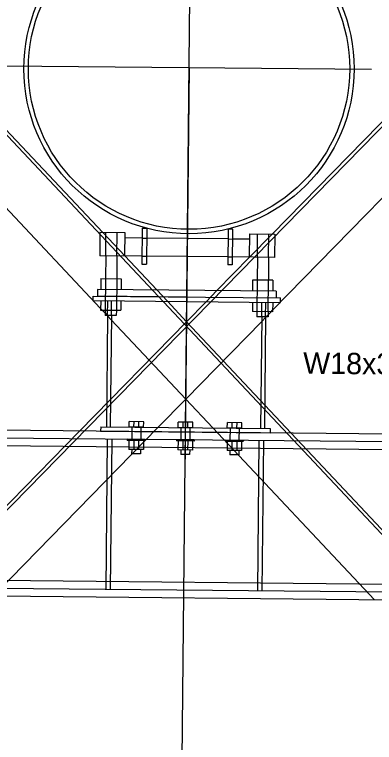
# Model space of a CAD drawing. Extents: x 632312 to 632885, y 378199 to 378534.
# Drawn here: x 632344.73 to 632348.09, y 378386.07 to 378392.88 of the extents above; entities that cross this region are included whole.
import ezdxf

# ---------------------------------------------------------------- set-up
doc = ezdxf.new("R2010")
doc.units = 0
for name, color, linetype in [('B_Boring', 7, 'Continuous'), ('R_Proposed Const Limits Cut', 7, 'Continuous'), ('R_Road Edge of Shoulder', 7, 'Continuous'), ('SHT_Dimensions', 7, 'Continuous')]:
    doc.layers.add(name, color=color, linetype=linetype)

msp = doc.modelspace()

# ---------------------------------------------------------------- linework, layer by layer
at = {"layer": 'B_Boring'}
for p, q in [((632345.9195, 378390.881), (632345.9162, 378390.5452)), ((632345.9195, 378390.881), (632345.9606, 378390.8806)), ((632345.9606, 378390.8806), (632345.9573, 378390.5448)), ((632346.7211, 378390.873), (632346.7178, 378390.5372)), ((632346.7622, 378390.8726), (632346.7211, 378390.873)), ((632346.7622, 378390.8726), (632346.7588, 378390.5368)), ((632345.5242, 378390.8408), (632345.522, 378390.624)), ((632345.7583, 378390.8385), (632345.5242, 378390.8408)), ((632345.7561, 378390.6217), (632345.7583, 378390.8385)), ((632345.9186, 378390.7881), (632345.7578, 378390.7897)), ((632346.7202, 378390.7801), (632345.9597, 378390.7877)), ((632346.922, 378390.7781), (632346.7612, 378390.7797)), ((632346.9204, 378390.6101), (632346.9225, 378390.8269)), ((632346.9225, 378390.8269), (632347.1566, 378390.8246)), ((632347.1566, 378390.8246), (632347.1545, 378390.6078)), ((632345.9169, 378390.6201), (632345.522, 378390.624)), ((632345.5776, 378390.6235), (632345.5754, 378390.41)), ((632345.6824, 378390.6224), (632345.6802, 378390.4089)), ((632346.7185, 378390.6121), (632345.958, 378390.6197)), ((632347.1545, 378390.6078), (632346.7596, 378390.6117)), ((632346.9942, 378390.6094), (632346.992, 378390.3959)), ((632347.0989, 378390.6083), (632347.0968, 378390.3949)), ((632345.9162, 378390.5452), (632345.9573, 378390.5448)), ((632346.7588, 378390.5368), (632346.7178, 378390.5372)), ((632345.5332, 378390.4104), (632345.5322, 378390.3083)), ((632345.5332, 378390.4104), (632345.7224, 378390.4085)), ((632345.7224, 378390.4085), (632345.7214, 378390.3064)), ((632346.9498, 378390.3963), (632346.9488, 378390.2942)), ((632347.139, 378390.3944), (632346.9498, 378390.3963)), ((632347.139, 378390.3944), (632347.138, 378390.2923)), ((632345.5018, 378390.3086), (632345.5012, 378390.2454)), ((632347.1684, 378390.292), (632345.5018, 378390.3086)), ((632345.4591, 378390.2041), (632345.4595, 378390.2458)), ((632345.4595, 378390.2458), (632347.2094, 378390.2284)), ((632347.1684, 378390.292), (632347.1678, 378390.2288)), ((632345.4591, 378390.2041), (632347.209, 378390.1867)), ((632345.5312, 378390.2034), (632345.5303, 378390.1154)), ((632345.7204, 378390.2015), (632345.7195, 378390.1135)), ((632346.9478, 378390.1893), (632346.9469, 378390.1013)), ((632347.137, 378390.1874), (632347.1361, 378390.0994)), ((632347.209, 378390.1867), (632347.2094, 378390.2284)), ((632345.5303, 378390.1154), (632345.7195, 378390.1135)), ((632345.5725, 378390.115), (632345.572, 378390.0659)), ((632345.6773, 378390.1139), (632345.6768, 378390.0649)), ((632347.1361, 378390.0994), (632346.9469, 378390.1013)), ((632346.9891, 378390.1009), (632346.9886, 378390.0519)), ((632347.0939, 378390.0998), (632347.0934, 378390.0508)), ((632345.6768, 378390.0649), (632345.572, 378390.0659)), ((632345.5952, 378390.0657), (632345.5849, 378389.0232)), ((632345.6307, 378390.0654), (632345.6203, 378389.0228)), ((632347.0934, 378390.0508), (632346.9886, 378390.0519)), ((632347.0348, 378390.0514), (632347.0244, 378389.0089)), ((632347.0702, 378390.051), (632347.0598, 378389.0085)), ((632345.7963, 378389.0211), (632345.7969, 378389.0732)), ((632345.9322, 378389.0718), (632345.7969, 378389.0732)), ((632345.8415, 378389.0206), (632345.842, 378389.0727)), ((632351.8217, 378388.9195), (632340.8222, 378389.0289)), ((632345.5307, 378389.0237), (632345.5303, 378388.982)), ((632345.5307, 378389.0237), (632347.114, 378389.008)), ((632345.9317, 378389.0197), (632345.7963, 378389.0211)), ((632345.8224, 378389.0208), (632345.8212, 378388.9067)), ((632345.8866, 378389.0202), (632345.8871, 378389.0723)), ((632345.9057, 378389.02), (632345.9046, 378388.9058)), ((632345.9317, 378389.0197), (632345.9322, 378389.0718)), ((632346.2546, 378389.0165), (632346.2552, 378389.0686)), ((632346.39, 378389.0152), (632346.2546, 378389.0165)), ((632346.3906, 378389.0673), (632346.2552, 378389.0686)), ((632346.2807, 378389.0163), (632346.2795, 378388.9021)), ((632346.2998, 378389.0161), (632346.3003, 378389.0682)), ((632346.3449, 378389.0156), (632346.3454, 378389.0677)), ((632346.364, 378389.0155), (632346.3629, 378388.9013)), ((632346.39, 378389.0152), (632346.3906, 378389.0673)), ((632346.713, 378389.012), (632346.7135, 378389.0641)), ((632346.8484, 378389.0106), (632346.713, 378389.012)), ((632346.8489, 378389.0627), (632346.7135, 378389.0641)), ((632346.739, 378389.0117), (632346.7379, 378388.8976)), ((632346.7581, 378389.0115), (632346.7586, 378389.0636)), ((632346.8032, 378389.0111), (632346.8037, 378389.0632)), ((632346.8223, 378389.0109), (632346.8212, 378388.8967)), ((632346.8484, 378389.0106), (632346.8489, 378389.0627)), ((632347.114, 378389.008), (632347.1135, 378388.9663)), ((632351.8209, 378388.847), (632340.8215, 378388.9564)), ((632345.5303, 378388.9821), (632347.1135, 378388.9663)), ((632345.5921, 378388.909), (632345.5781, 378387.504)), ((632345.6337, 378388.9085), (632345.6198, 378387.5036)), ((632345.7796, 378388.9071), (632345.7795, 378388.8967)), ((632345.9461, 378388.895), (632345.7795, 378388.8967)), ((632345.9462, 378388.9054), (632345.7796, 378388.9071)), ((632345.7951, 378388.8965), (632345.7943, 378388.8132)), ((632345.8402, 378388.8961), (632345.8394, 378388.8127)), ((632345.8854, 378388.8956), (632345.8845, 378388.8123)), ((632345.9305, 378388.8952), (632345.9297, 378388.8118)), ((632345.9462, 378388.9054), (632345.9461, 378388.895)), ((632346.2379, 378388.9025), (632346.2378, 378388.8921)), ((632346.4044, 378388.8905), (632346.2378, 378388.8921)), ((632346.4045, 378388.9009), (632346.2379, 378388.9025)), ((632346.2534, 378388.892), (632346.2526, 378388.8086)), ((632346.2985, 378388.8915), (632346.2977, 378388.8082)), ((632346.3437, 378388.8911), (632346.3428, 378388.8077)), ((632346.3888, 378388.8906), (632346.388, 378388.8073)), ((632346.4045, 378388.9009), (632346.4044, 378388.8905)), ((632346.6962, 378388.898), (632346.6961, 378388.8876)), ((632346.8627, 378388.8859), (632346.6961, 378388.8876)), ((632346.8628, 378388.8963), (632346.6962, 378388.898)), ((632346.7117, 378388.8874), (632346.7109, 378388.8041)), ((632346.7568, 378388.887), (632346.756, 378388.8036)), ((632346.802, 378388.8865), (632346.8012, 378388.8032)), ((632346.8471, 378388.8861), (632346.8463, 378388.8027)), ((632346.8628, 378388.8963), (632346.8627, 378388.8859)), ((632347.0087, 378388.8949), (632346.9947, 378387.4899)), ((632347.0503, 378388.8945), (632347.0364, 378387.4895)), ((632345.9297, 378388.8118), (632345.7943, 378388.8132)), ((632345.8203, 378388.8129), (632345.8199, 378388.7713)), ((632345.9036, 378388.8121), (632345.9032, 378388.7704)), ((632346.388, 378388.8073), (632346.2526, 378388.8086)), ((632346.2786, 378388.8084), (632346.2782, 378388.7667)), ((632346.3619, 378388.8075), (632346.3615, 378388.7659)), ((632346.8463, 378388.8027), (632346.7109, 378388.8041)), ((632346.7369, 378388.8038), (632346.7365, 378388.7622)), ((632346.8203, 378388.803), (632346.8198, 378388.7613)), ((632345.9032, 378388.7704), (632345.8199, 378388.7713)), ((632346.3615, 378388.7659), (632346.2782, 378388.7667)), ((632346.8198, 378388.7613), (632346.7365, 378388.7622)), ((632351.807, 378387.4421), (632340.8075, 378387.5515)), ((632351.8062, 378387.3696), (632340.8068, 378387.479))]:
    msp.add_line(p, q, dxfattribs=at)
for points in [[(632347.1362, 378390.1143), (632350.9136, 378393.9818), (632350.5559, 378394.3312), (632347.1313, 378390.8248)], [(632344.6417, 378391.8078), (632345.5495, 378390.8406)], [(632345.5305, 378390.1302), (632344.6345, 378391.0849)], [(632345.7549, 378390.6217), (632346.054, 378390.3031)], [(632346.9216, 378390.6101), (632346.6163, 378390.2975)], [(632346.5148, 378390.1936), (632346.3322, 378390.0067), (632345.3334, 378388.984)], [(632346.1533, 378390.1972), (632346.3322, 378390.0067)], [(632345.5722, 378390.0858), (632345.5446, 378390.1152)], [(632347.0936, 378390.0706), (632347.1218, 378390.0995)], [(632345.5952, 378390.0613), (632345.591, 378390.0657)], [(632347.0701, 378390.0466), (632347.0744, 378390.051)], [(632345.9825, 378389.6486), (632345.6302, 378390.0239)], [(632346.0659, 378389.0184), (632346.325, 378389.2837), (632347.0343, 378390.01)], [(632346.6747, 378389.6417), (632347.3104, 378388.9644)], [(632346.5788, 378389.0133), (632346.325, 378389.2837)]]:
    msp.add_lwpolyline(points, dxfattribs=at)
for radius in [1.5417, 1.5]:
    msp.add_circle((632346.3557, 378392.3708), radius, dxfattribs=at)
at = {"layer": 'R_Proposed Const Limits Cut'}
for p, q in [((632342.1725, 378394.3929), (632350.8037, 378385.1968)), ((632350.5783, 378394.3094), (632341.7659, 378385.2867)), ((632345.7561, 378390.6217), (632345.5495, 378390.8406)), ((632345.5776, 378390.6235), (632345.5797, 378390.8403)), ((632345.6824, 378390.6224), (632345.6845, 378390.8392)), ((632345.9186, 378390.7881), (632345.9597, 378390.7877)), ((632346.7202, 378390.7801), (632346.7612, 378390.7797)), ((632346.9216, 378390.6101), (632347.1313, 378390.8248)), ((632346.9942, 378390.6094), (632346.9963, 378390.8262)), ((632347.0989, 378390.6083), (632347.1011, 378390.8251)), ((632345.9169, 378390.6201), (632345.958, 378390.6197)), ((632346.7185, 378390.6121), (632346.7596, 378390.6117)), ((632345.5754, 378390.41), (632345.5725, 378390.115)), ((632345.6802, 378390.4089), (632345.6773, 378390.1139)), ((632346.992, 378390.3959), (632346.9891, 378390.1009)), ((632347.0939, 378390.0998), (632347.0968, 378390.3949)), ((632346.1533, 378390.1972), (632346.054, 378390.3031)), ((632346.5148, 378390.1936), (632346.6163, 378390.2975)), ((632345.5952, 378390.0657), (632345.5966, 378390.2028)), ((632345.6307, 378390.0654), (632345.632, 378390.2024)), ((632347.0348, 378390.0514), (632347.0361, 378390.1884)), ((632347.0702, 378390.051), (632347.0715, 378390.1881)), ((632345.5305, 378390.1302), (632345.5446, 378390.1152)), ((632347.1218, 378390.0995), (632347.1362, 378390.1143)), ((632345.5722, 378390.0858), (632345.591, 378390.0657)), ((632345.5952, 378390.0613), (632345.6302, 378390.0239)), ((632347.0343, 378390.01), (632347.0701, 378390.0466)), ((632347.0744, 378390.051), (632347.0936, 378390.0706)), ((632346.6747, 378389.6417), (632346.3322, 378390.0067)), ((632345.9825, 378389.6486), (632346.325, 378389.2837)), ((632344.5262, 378387.442), (632346.0659, 378389.0184)), ((632346.5788, 378389.0133), (632348.0868, 378387.4066)), ((632345.3334, 378388.984), (632343.834, 378387.4489)), ((632347.3104, 378388.9644), (632348.779, 378387.3997)), ((632351.8202, 378388.7737), (632340.8208, 378388.8831)), ((632351.8077, 378387.5154), (632340.8082, 378387.6248))]:
    msp.add_line(p, q, dxfattribs=at)
at = {"layer": 'R_Road Edge of Shoulder'}
msp.add_line((632346.2256, 378379.2847), (632346.5561, 378412.5263), dxfattribs=at)
at = {"layer": 'SHT_Dimensions'}
for p, q in [((632344.6401, 378392.3999), (632348.0606, 378392.3659)), ((632346.3558, 378392.3828), (632346.3179, 378388.5712)), ((632346.3345, 378390.2371), (632345.5012, 378390.2454))]:
    msp.add_line(p, q, dxfattribs=at)

# ---------------------------------------------------------------- texts
msp.add_text('W18x35', height=0.2, rotation=359.43036, dxfattribs=at).set_placement((632347.4205, 378389.5205))

doc.saveas('drawing.dxf')
